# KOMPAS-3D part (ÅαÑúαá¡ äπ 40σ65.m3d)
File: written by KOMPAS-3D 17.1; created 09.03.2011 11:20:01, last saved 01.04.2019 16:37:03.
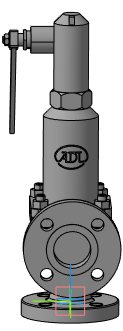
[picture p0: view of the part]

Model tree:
1. Операция без истории:1

Referenced files in C:\Users\tra\Desktop\Детали с марк. для Сферы\bsv\Desktop\Si 57\: VIC_496_40x65_3d.a3d
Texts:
  Viktor2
